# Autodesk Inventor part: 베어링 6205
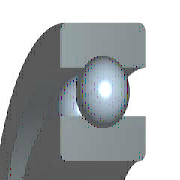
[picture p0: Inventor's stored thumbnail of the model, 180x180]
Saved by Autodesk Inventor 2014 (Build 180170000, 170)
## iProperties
Created: 2015-10
Part Number: 베어링 6205
Material: 강, 연강
Description: 깊은 그루브 볼 베어링
Document SubType Name: Modeling
Standard: KS B 2023
Designer: mdu
Standards Organization: KS
Language: ko-KR
Size Designation: 6205 - 25 x 52 x 15
Categories: <MemberInstance><Categories><Category DisplayName="샤프트 부품" InternalName="7f7aeb1f-a693-4053-b835-cee3144e0d98" Mnemonic="SHFT"><Category DisplayName="베어링" Inter
Density: 7.86 g/cm^3
Appearance: 강철
Mass: 116.729 g
Surface Area: 107.326 cm^2
Volume: 14.851 cm^3
IsCustomPart: 1
Author: mdu
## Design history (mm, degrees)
sketch "스케치" dims "d0" = 7.02 (= -0.26 x WD + 0.26 x BD)
  geometry: L1 (3.99, 19.25)-(11.01, 19.25); L2 (7.5, 19.25)-(7.5, 15.74); L3 (7.5, 19.25)-(7.5, 22.76); L4 (4.892, 16.901)-(0, 16.901); L5 (0, 12.5)-(15, 12.5); L6 (4.892, 21.599)-(0, 21.599); L7 (0, 26)-(15, 26); L8 (15, 12.5)-(15, 16.901); L9 (10.108, 16.901)-(15, 16.901); L10 (10.108, 21.599)-(15, 21.599); L11 (15, 26)-(15, 21.599); L12 (-1.4, 0)-(8.4, 0) reference; L13 (0, -0.3)-(0, 5.3) reference
  constraints: 22 end point, 4 point on line, 2 collinear, 2 perpendicular, 2 symmetric about line, 1 midpoint, 1 parallel, 14 other
  dimensions: "d9" = 25 diameter of L5 L12 (= WD); "d11" = 52 diameter of L7 L12 (= BD); "d12" = 15 distance between parallel lines of L8 L13 (= KB); "d13" = 33.802 diameter of L9 L12 (= 0.326 x BD + 0.674 x WD)
revolve "본체" stored, may be unused: angle "d6" = 90 deg
revolve "볼" stored, may be unused: angle "d7" = 90 deg
pattern_circular "IDS_ARRAYBALL[SIMPL:T]" dims angle "d3" = 360 deg
body "Solid1"
fillet "모깎기1" dims "d1" = 1 (= KRS)
other parameters: "WD" = 25 [user parameter; used in 5 equation terms], "BD" = 52 [user parameter; used in 5 equation terms], "KB" = 15 [user parameter; used in 1 equation term], "KRS" = 1 [user parameter; used in 1 equation term], "d4" = 0, "d5" = 0, "d8" = 0, "d14" = 0, "d15" = 0, "BBA" = 0 [user parameter], "BC0" = 7800000 [user parameter], "BC" = 1.4e+07 [user parameter], "BR" = 26 (= 0.5 x BD) [user parameter], "WR" = 12.5 (= 0.5 x WD) [user parameter]
